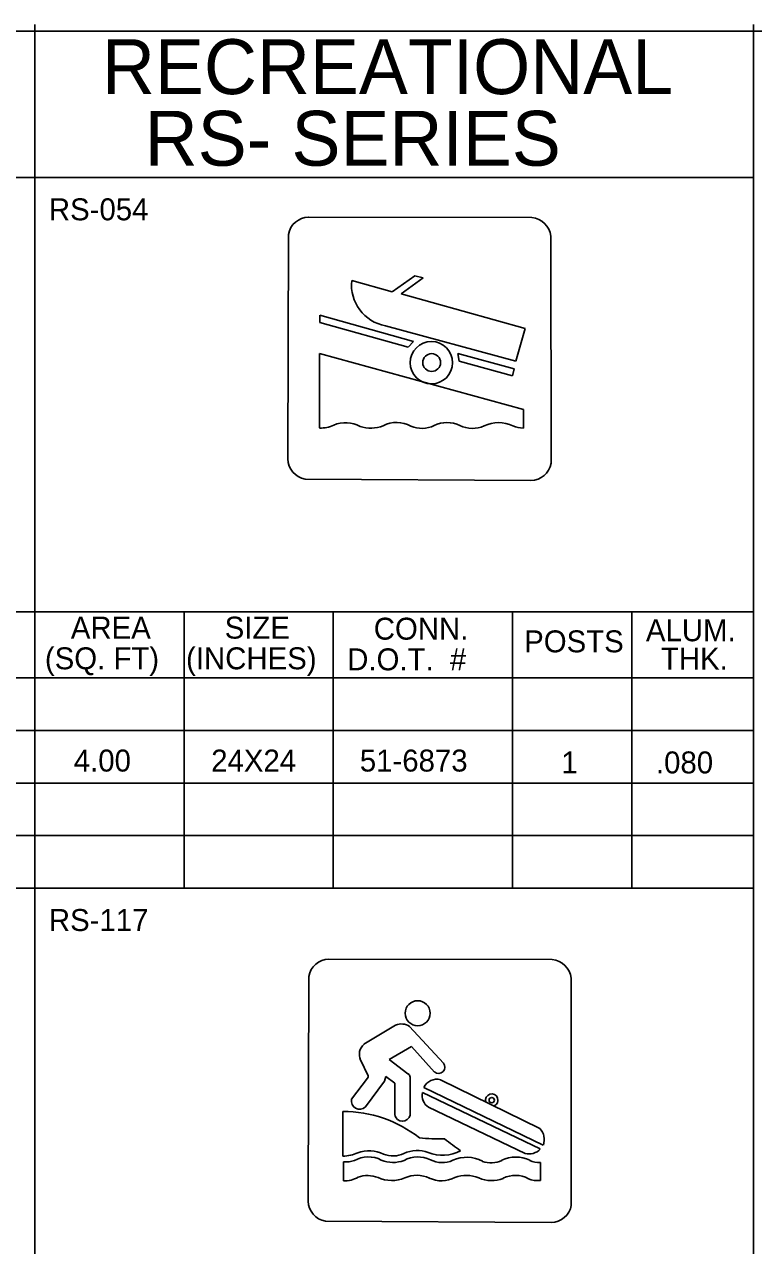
# Model space of a CAD drawing. Extents: x 0 to 2011, y -22 to 1183.
# Drawn here: x 841.5 to 947.8, y 652 to 830 of the extents above; entities that cross this region are included whole.
import ezdxf

# ---------------------------------------------------------------- set-up
doc = ezdxf.new("R2010")
doc.units = 0
for name, color, linetype in [('CT_Border_Perimeter_Shape', 7, 'Continuous'), ('CT_Construction', 7, 'Continuous'), ('Level 1', 7, 'Continuous'), ('Level 2', 7, 'Continuous'), ('Level 5', 7, 'Continuous')]:
    doc.layers.add(name, color=color, linetype=linetype)

msp = doc.modelspace()

# ---------------------------------------------------------------- linework, layer by layer
at = {"layer": 'CT_Border_Perimeter_Shape'}
msp.add_lwpolyline([(0, -0.97), (1270, -0.97), (1270, 829.03), (0, 829.03)], close=True, dxfattribs=at)
at = {"layer": 'CT_Construction'}
msp.add_lwpolyline([(0, 829.03), (1270, 829.03), (1270, 59.03), (0, 59.03)], close=True, dxfattribs=at)
at = {"layer": 'Level 1'}
for p, q in [((915.47, 801.83), (882.96, 801.91)), ((880.01, 799.39), (879.92, 766.64)), ((918.28, 766.01), (918.25, 799.14)), ((889.23, 792.65), (895.14, 791.03)), ((895.14, 791.03), (898.41, 793.34)), ((899.65, 793.03), (896.42, 790.72)), ((898.41, 793.34), (899.65, 793.03)), ((896.42, 790.72), (914.49, 785.69)), ((898.22, 783.78), (884.56, 787.61)), ((884.56, 787.61), (884.56, 786.52)), ((884.56, 786.52), (897.46, 782.93)), ((913.16, 780.91), (894.14, 786.04)), ((914.49, 785.69), (913.16, 780.91)), ((897.46, 782.93), (898.22, 783.78)), ((884.54, 771.16), (884.51, 782.03)), ((884.51, 782.03), (914.24, 773.86)), ((904.71, 782), (912.91, 779.77)), ((904.89, 780.89), (904.71, 782)), ((912.67, 778.75), (904.89, 780.89)), ((912.91, 779.77), (912.67, 778.75)), ((914.24, 773.86), (914.24, 771.15)), ((882.45, 763.69), (915.33, 763.49)), ((918.42, 693.65), (885.91, 693.72)), ((882.97, 691.2), (882.88, 658.45)), ((921.23, 657.83), (921.21, 690.95)), ((895.63, 684.08), (891.01, 681.3)), ((902.6, 678.56), (897.67, 683.9)), ((894.7, 679.1), (897.95, 681)), ((897.95, 681), (901.3, 677.26)), ((890.53, 679.02), (891.64, 676.71)), ((897.43, 677.02), (894.7, 679.1)), ((894.03, 675.91), (894.19, 676.63)), ((894.19, 676.63), (895.49, 675.64)), ((891.54, 676.39), (889.2, 673.31)), ((891.22, 672.17), (894.03, 675.91)), ((895.49, 675.64), (895.49, 671)), ((897.74, 670.97), (897.74, 676.5)), ((917.15, 666.62), (899.74, 675.03)), ((902.19, 676.14), (916.64, 669.02)), ((916.71, 666.04), (899.55, 674.28)), ((887.95, 665.01), (887.95, 671.51)), ((900.4, 672.12), (914.48, 665.4)), ((888.04, 664.16), (888.04, 661.38)), ((916.72, 661.43), (916.72, 664.07)), ((885.4, 655.51), (918.29, 655.3))]:
    msp.add_line(p, q, dxfattribs=at)
for centre, radius in [((900.84, 780.68), 3.09), ((900.88, 780.7), 1.3), ((898.84, 685.84), 1.82), ((909.63, 673.16), 0.388)]:
    msp.add_circle(centre, radius, dxfattribs=at)
for centre, radius, start, end in [((883.03, 798.84), 3.07, 91.4217, 169.7213), ((915.2, 798.77), 3.07, 6.7762, 85.0758), ((895.28, 792.03), 6.09, 174.1028, 259.2139), ((884.72, 775.54), 4.39, 267.5645, 295.5476), ((888.34, 767.46), 4.47, 61.8133, 112.7532), ((892.01, 775.83), 4.7, 250.6507, 292.461), ((895.76, 767.66), 4.31, 61.0182, 117.048), ((899.43, 775.25), 4.15, 247.4997, 295.889), ((903.12, 767.66), 4.29, 64.3173, 115.9152), ((906.82, 775.29), 4.19, 243.9967, 294.3106), ((910.64, 767.06), 4.89, 64.7233, 115.3716), ((914.17, 774.48), 3.33, 244.223, 271.185), ((882.99, 766.72), 3.07, 181.4217, 259.7213), ((915.26, 766.56), 3.07, 271.4217, 349.7213), ((885.99, 690.65), 3.07, 91.4217, 169.7213), ((918.16, 690.59), 3.07, 6.7762, 85.0758), ((896.49, 682.24), 2.03, 54.7138, 114.9884), ((892.24, 679.84), 1.9, 130.1383, 205.8026), ((901.88, 677.99), 0.925, 231.4213, 38.6045), ((891.18, 676.68), 0.464, 320.3528, 2.7928), ((897.06, 676.45), 0.685, 4.1794, 56.7745), ((901.65, 674.08), 2.13, 75.2804, 153.6392), ((890.38, 673.04), 1.21, 167.4488, 313.5276), ((901.49, 673.8), 1.99, 165.9996, 237.1134), ((909.63, 673.16), 0.915, 291.8102, 195.7741), ((887.94, 653.43), 18.09, 51.9517, 89.9696), ((896.62, 671.25), 1.16, 192.8014, 345.8471), ((902.11, 695.13), 27.62, 263.7046, 271.314), ((914.95, 667.41), 2.34, 340.2533, 43.6272), ((919.64, 688.08), 26.61, 230.5979, 236.8698), ((915.06, 667.58), 2.26, 254.9343, 316.9219), ((887.98, 669.9), 4.89, 269.5403, 295.7912), ((888.31, 668.51), 4.36, 266.3716, 287.4017), ((891.65, 660.79), 4.1, 62.5946, 119.6878), ((891.76, 661.13), 4.66, 63.3047, 110.7331), ((895.27, 668.59), 4.51, 247.3562, 290.5487), ((895.25, 668.55), 3.53, 246.7794, 296.6399), ((898.75, 661.34), 4.48, 68.6061, 115.307), ((898.87, 660.71), 4.18, 64.0331, 118.8065), ((902.45, 670.57), 5.46, 247.8018, 298.9466), ((902.41, 667.93), 3.87, 243.7182, 293.7613), ((905.98, 660.07), 4.77, 61.0751, 114.9238), ((909.53, 667.7), 3.68, 250.233, 295.3184), ((913.14, 660.33), 4.54, 63.4348, 116.6721), ((916.61, 667.55), 3.48, 245.5732, 271.8378), ((888.16, 665.29), 3.91, 268.1533, 300.5577), ((891.54, 658.2), 3.97, 67.4011, 110.5147), ((895.07, 666.3), 4.86, 245.7425, 292.8345), ((898.73, 657.81), 4.39, 65.5697, 113.8419), ((902.3, 665.47), 4.07, 244.3278, 298.4907), ((905.9, 657.43), 4.76, 67.1694, 110.3496), ((909.6, 666.05), 4.62, 246.3328, 291.716), ((913.09, 658.34), 3.86, 60.6812, 117.5263), ((916.45, 665.34), 3.92, 248.0149, 273.8925), ((885.95, 658.53), 3.07, 181.4217, 259.7213), ((918.21, 658.37), 3.07, 271.4217, 349.7213)]:
    msp.add_arc(centre, radius, start, end, dxfattribs=at)
at = {"layer": 'Level 2'}
for p, q in [((738.29, 744.34), (843.04, 744.34)), ((843.04, 744.34), (947.79, 744.34)), ((864.79, 744.34), (864.79, 704.06)), ((886.54, 744.34), (886.54, 704.06)), ((912.64, 744.34), (912.64, 704.06)), ((930.04, 744.34), (930.04, 704.06)), ((738.29, 734.75), (843.04, 734.75)), ((843.04, 734.75), (947.79, 734.75)), ((738.29, 727.07), (843.04, 727.07)), ((843.04, 727.07), (947.79, 727.07)), ((738.29, 719.4), (843.04, 719.4)), ((843.04, 719.4), (947.79, 719.4)), ((738.29, 711.73), (843.04, 711.73)), ((843.04, 711.73), (947.79, 711.73))]:
    msp.add_line(p, q, dxfattribs=at)
for points in [[(843.04, 807.68), (738.29, 807.68), (738.29, 704.06), (843.04, 704.06)], [(947.79, 807.68), (843.04, 807.68), (843.04, 704.06), (947.79, 704.06)], [(947.79, 704.06), (843.04, 704.06), (843.04, 600.44), (947.79, 600.44)]]:
    msp.add_lwpolyline(points, close=True, dxfattribs=at)
at = {"layer": 'Level 5'}
for p, q in [((843.04, 830), (843.04, 600.44)), ((843.04, 830), (843.04, 496.81)), ((947.79, 830), (947.79, 496.81))]:
    msp.add_line(p, q, dxfattribs=at)

# ---------------------------------------------------------------- texts
at = {"layer": 'Level 1'}
for s, p in [('RECREATIONAL', (852.83, 819.84)), ('RS- SERIES', (859.06, 809.4))]:
    msp.add_text(s, height=8, dxfattribs=at).set_placement(p)
at = {"layer": 'Level 2'}
for s, p in [('RS-054', (845.1, 801.44)), ('AREA', (848.3, 740.45)), ('SIZE', (870.72, 740.45)), ('CONN.', (892.44, 740.3)), ('ALUM.', (932.1, 740.07)), ('POSTS', (914.36, 738.45)), ('(SQ. FT)', (844.52, 735.98)), ('(INCHES)', (865.09, 735.98)), ('D.O.T.  #', (888.57, 735.83)), ('THK.', (934.28, 735.93)), ('RS-117', (845.1, 697.82))]:
    msp.add_text(s, height=3.2, dxfattribs=at).set_placement(p)
at = {"layer": 'Level 5'}
for s, p in [(' 4.00', (847.54, 721.07)), ('24X24', (868.75, 721.07)), ('51-6873', (890.41, 721.07)), ('1', (919.77, 720.8)), ('.080', (933.56, 720.8))]:
    msp.add_text(s, height=3.2, dxfattribs=at).set_placement(p)

doc.saveas('drawing.dxf')
